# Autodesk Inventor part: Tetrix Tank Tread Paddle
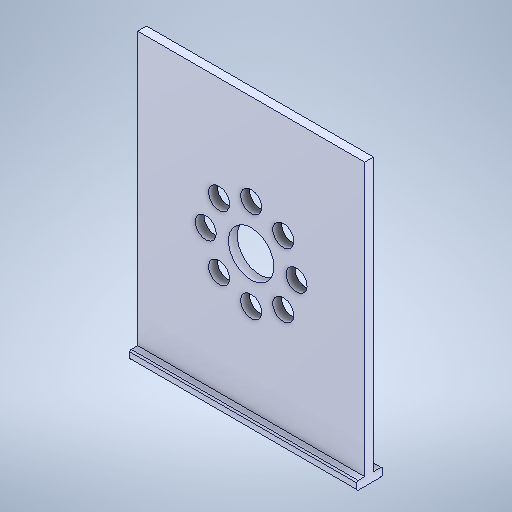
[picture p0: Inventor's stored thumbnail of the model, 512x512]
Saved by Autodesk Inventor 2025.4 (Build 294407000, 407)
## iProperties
Created: 2021-10
Part Number: Tetrix Tank Tread Paddle
Material: Genérico
Document SubType Name: Modeling
Designer: usuario
Density: 1 g/cm^3
Appearance: Valor por defecto
Author: usuario
Sending System: SolidWorks 2016
Last Author: LENOVO
Last Saved: 2021-10-21
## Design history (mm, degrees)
fillet "Fillet1"
node "Plane1"
node "Sólido1"
